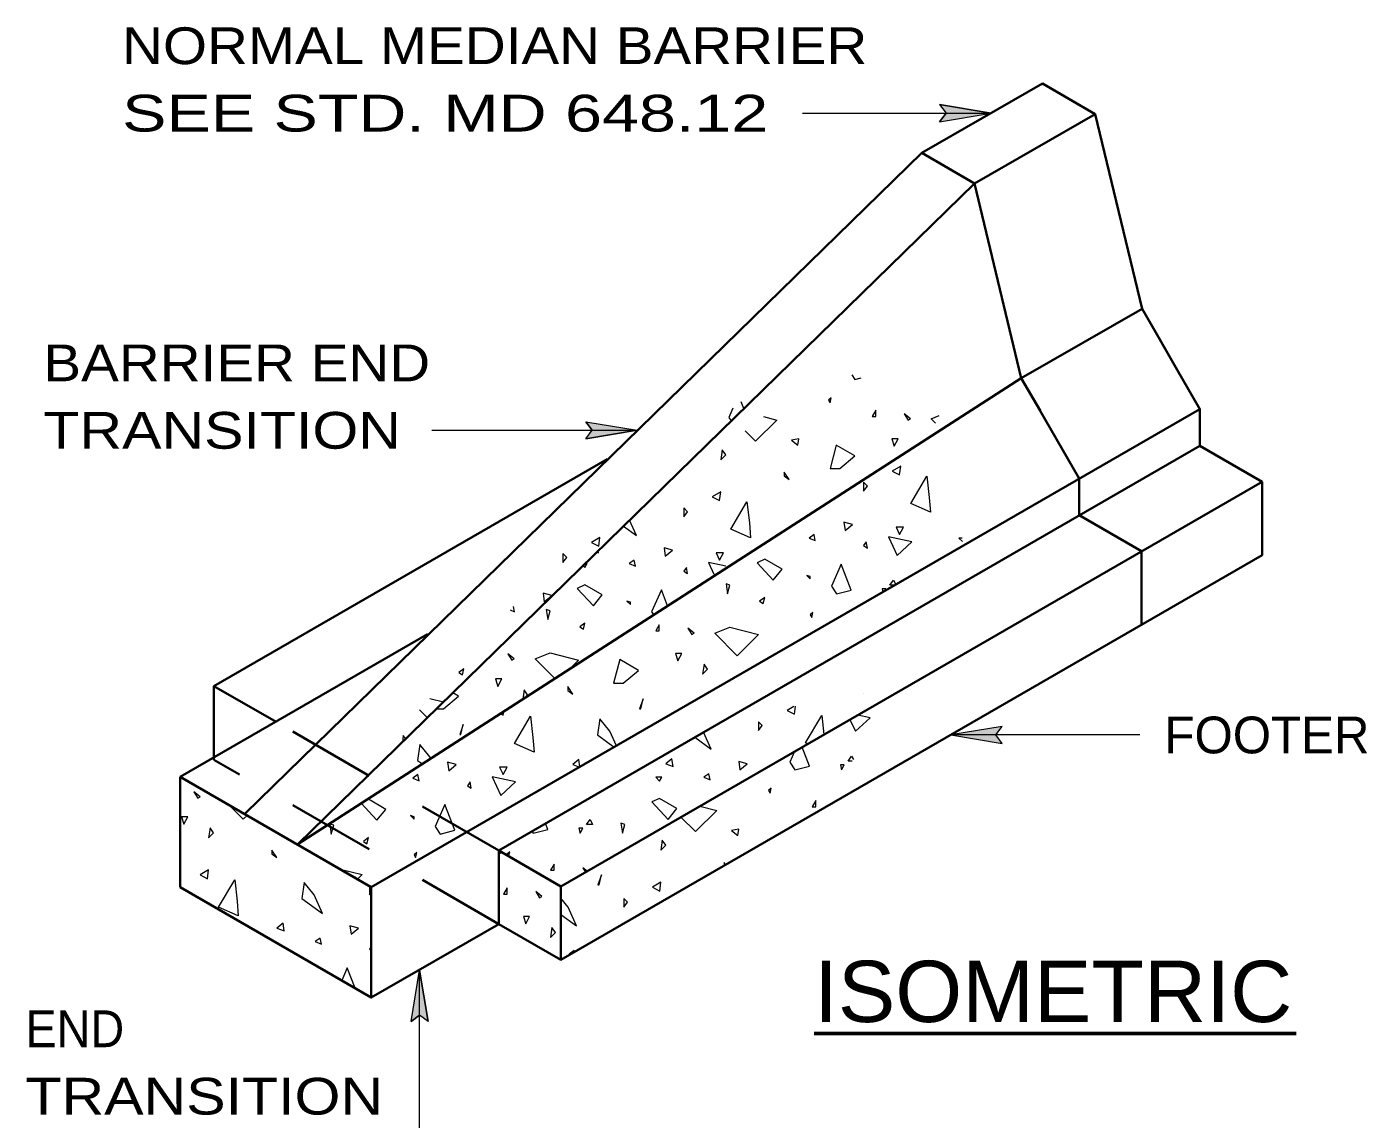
# Model space of a CAD drawing. Extents: x -11.7 to -4.5, y 8.6 to 18.8.
# Drawn here: x -11.741 to -9.555, y 17.003 to 18.786 of the extents above; entities that cross this region are included whole.
import ezdxf
from ezdxf.enums import TextEntityAlignment as Align

# ---------------------------------------------------------------- set-up
doc = ezdxf.new("R2010")
doc.units = 0
doc.header["$LTSCALE"] = 0.024
doc.linetypes.add('LONG_DASHED', pattern=[7.5, 6, -1.5])
for name, color, linetype, lineweight in [('1', 7, 'Continuous', 35), ('10', 7, 'Continuous', 13), ('12', 7, 'Continuous', 53), ('6', 7, 'Continuous', 13)]:
    doc.layers.add(name, color=color, linetype=linetype, lineweight=lineweight)

msp = doc.modelspace()

# ---------------------------------------------------------------- hatches: boundary and pattern name
at = {"layer": '10'}
for points in [[(-10.1685, 18.64483), (-10.2525, 18.65883), (-10.242, 18.64483), (-10.2525, 18.63083)], [(-10.74567, 18.12733), (-10.82967, 18.11333), (-10.81917, 18.12733), (-10.82967, 18.14133)], [(-10.15033, 17.64433), (-10.23433, 17.63033), (-10.15033, 17.61633), (-10.16083, 17.63033)], [(-11.1005, 17.24683), (-11.0865, 17.16283), (-11.1005, 17.17333), (-11.1145, 17.16283)]]:
    msp.add_hatch(color=256, dxfattribs=at).paths.add_polyline_path(points)

# ---------------------------------------------------------------- linework, layer by layer
at = {"layer": '1'}
for p, q in [((-10.08467, 18.693), (-10.28133, 18.57983)), ((-9.99883, 18.64333), (-10.08467, 18.693)), ((-9.9225, 18.32567), (-9.99883, 18.64333)), ((-10.28133, 18.57983), (-11.385, 17.502)), ((-10.1955, 18.53017), (-10.28133, 18.57983)), ((-9.9225, 18.32567), (-10.11933, 18.2125)), ((-9.892, 18.27283), (-9.9225, 18.32567)), ((-10.11933, 18.2125), (-11.29917, 17.45233)), ((-9.72683, 18.0435), (-9.828, 18.102)), ((-10.87017, 17.38333), (-9.72683, 18.0435)), ((-10.02483, 17.98883), (-10.02483, 18.04883)), ((-9.9235, 17.93033), (-10.02483, 17.98883)), ((-9.9235, 17.81033), (-9.9235, 17.93033)), ((-11.49117, 17.56183), (-11.0875, 17.795)), ((-11.436, 17.59), (-11.436, 17.71)), ((-11.17933, 17.38183), (-11.49117, 17.56183)), ((-11.49117, 17.38183), (-11.49117, 17.56183)), ((-11.17933, 17.20183), (-11.49117, 17.38183)), ((-10.87017, 17.26333), (-10.87017, 17.38333))]:
    msp.add_line(p, q, dxfattribs=at)
at = {"layer": '1', "linetype": 'LONG_DASHED'}
for p, q in [((-10.97133, 17.44183), (-11.334, 17.65117)), ((-10.97133, 17.32183), (-11.436, 17.59))]:
    msp.add_line(p, q, dxfattribs=at)
at = {"layer": '1'}
for points in [[(-9.99883, 18.64333), (-10.1955, 18.53017), (-11.29917, 17.45233)], [(-10.08867, 18.15967), (-10.11933, 18.2125), (-10.1955, 18.53017)], [(-9.828, 18.102), (-9.828, 18.162), (-9.86517, 18.22617), (-9.90217, 18.2905)], [(-10.02483, 18.04883), (-10.06183, 18.113), (-10.099, 18.17717)], [(-10.97133, 17.32183), (-11.17933, 17.20183), (-11.17933, 17.38183), (-9.828, 18.162)], [(-10.87017, 17.38333), (-10.97133, 17.44183), (-9.828, 18.102)], [(-11.33467, 17.6515), (-11.436, 17.71), (-10.7945, 18.08033)], [(-10.87017, 17.26333), (-9.72683, 17.9235), (-9.72683, 18.0435)], [(-10.87017, 17.26333), (-10.97133, 17.32183), (-10.97133, 17.44183)]]:
    msp.add_lwpolyline(points, dxfattribs=at)
at = {"layer": '10'}
for p, q in [((-10.2525, 18.65883), (-10.1685, 18.64483)), ((-10.2525, 18.65883), (-10.242, 18.64483)), ((-10.476, 18.64483), (-10.1685, 18.64483)), ((-10.2525, 18.63083), (-10.1685, 18.64483)), ((-10.2525, 18.63083), (-10.242, 18.64483)), ((-11.08067, 18.12733), (-10.74567, 18.12733)), ((-10.82967, 18.14133), (-10.74567, 18.12733)), ((-10.82967, 18.14133), (-10.81917, 18.12733)), ((-10.82967, 18.11333), (-10.74567, 18.12733)), ((-10.82967, 18.11333), (-10.81917, 18.12733)), ((-9.926, 17.63033), (-10.23433, 17.63033)), ((-11.1145, 17.16283), (-11.1005, 17.24683)), ((-11.0865, 17.16283), (-11.1005, 17.24683)), ((-11.1145, 17.16283), (-11.1005, 17.17333)), ((-11.0865, 17.16283), (-11.1005, 17.17333))]:
    msp.add_line(p, q, dxfattribs=at)
for points in [[(-10.1685, 18.64483), (-10.2525, 18.65883), (-10.242, 18.64483), (-10.2525, 18.63083)], [(-10.74567, 18.12733), (-10.82967, 18.11333), (-10.81917, 18.12733), (-10.82967, 18.14133)], [(-10.15033, 17.64433), (-10.23433, 17.63033), (-10.15033, 17.61633), (-10.16083, 17.63033)], [(-11.1005, 17.24683), (-11.0865, 17.16283), (-11.1005, 17.17333), (-11.1145, 17.16283)]]:
    msp.add_lwpolyline(points, close=True, dxfattribs=at)
msp.add_lwpolyline([(-11.54833, 16.931), (-11.1005, 16.931), (-11.1005, 17.24683)], dxfattribs=at)
at = {"layer": '12'}
msp.add_line((-10.45717, 17.1435), (-9.671, 17.1435), dxfattribs=at)
at = {"layer": '6'}
for p, q in [((-10.49, 18.243), (-10.48983, 18.24267)), ((-10.48733, 18.245), (-10.4875, 18.245)), ((-10.57183, 18.16267), (-10.57633, 18.174)), ((-11.08383, 17.68983), (-11.06167, 17.68417)), ((-11.08783, 17.6585), (-11.1005, 17.67117)), ((-11.17933, 17.38117), (-11.181, 17.38283))]:
    msp.add_line(p, q, dxfattribs=at)
for points in [[(-10.39567, 18.21767), (-10.39083, 18.21033), (-10.38067, 18.21317)], [(-10.58967, 18.16333), (-10.59617, 18.1485), (-10.59233, 18.14267)], [(-10.53967, 18.14967), (-10.51817, 18.14417), (-10.55267, 18.10967), (-10.56983, 18.12667)], [(-10.25917, 18.139), (-10.26617, 18.146), (-10.25317, 18.15133)], [(-10.76783, 17.97117), (-10.74667, 17.956), (-10.758, 17.98067)], [(-10.21583, 17.95167), (-10.221, 17.95167), (-10.21517, 17.94583)], [(-10.8115, 17.9285), (-10.809, 17.92767), (-10.8095, 17.9305)], [(-10.834, 17.9065), (-10.83117, 17.90367), (-10.82733, 17.90983), (-10.8305, 17.90983)], [(-10.60133, 17.90583), (-10.6295, 17.91183), (-10.6205, 17.89283)], [(-10.32533, 17.87483), (-10.33383, 17.87483), (-10.328, 17.883), (-10.32417, 17.87567)], [(-10.69633, 17.84117), (-10.70633, 17.86717), (-10.72217, 17.83117), (-10.71883, 17.82617)], [(-10.34167, 17.86533), (-10.34, 17.86867), (-10.34633, 17.86867), (-10.34517, 17.8635)], [(-10.95283, 17.83433), (-10.94567, 17.83117), (-10.94733, 17.84017)], [(-10.88017, 17.72233), (-10.91233, 17.75433), (-10.88783, 17.7645), (-10.84117, 17.75233), (-10.85567, 17.738)], [(-10.52083, 17.762), (-10.524, 17.7615), (-10.523, 17.76083)], [(-11.07283, 17.67317), (-11.0615, 17.67317), (-11.03717, 17.69383), (-11.04633, 17.69917)], [(-10.92983, 17.69017), (-10.92433, 17.69583), (-10.93, 17.704), (-10.93233, 17.68867)], [(-10.37617, 17.69867), (-10.37617, 17.6985), (-10.37617, 17.69867)], [(-10.96883, 17.665), (-10.96417, 17.66267), (-10.96333, 17.66867)], [(-10.49017, 17.67683), (-10.50133, 17.67017), (-10.48933, 17.664), (-10.48767, 17.67733)], [(-10.4675, 17.61583), (-10.47117, 17.6175), (-10.44483, 17.662), (-10.44133, 17.631)], [(-10.39883, 17.6555), (-10.38983, 17.63633), (-10.36583, 17.6585), (-10.38617, 17.66283)], [(-10.7795, 17.61267), (-10.79033, 17.63633), (-10.80667, 17.6565), (-10.8105, 17.6305), (-10.783, 17.61067)], [(-11.12317, 17.624), (-11.12717, 17.62967), (-11.12867, 17.61867)], [(-10.6515, 17.62667), (-10.62483, 17.60733), (-10.63733, 17.63483)], [(-11.0825, 17.59183), (-11.08367, 17.5945), (-11.1, 17.61467), (-11.10383, 17.58867), (-11.096, 17.58317)], [(-10.48933, 17.60333), (-10.49683, 17.586), (-10.48867, 17.5735), (-10.46467, 17.57967), (-10.47667, 17.61067)], [(-10.39517, 17.58783), (-10.40183, 17.58783), (-10.396, 17.596), (-10.39317, 17.5905)], [(-10.839, 17.57833), (-10.84083, 17.59017), (-10.85083, 17.582), (-10.83967, 17.578)], [(-11.38183, 17.49883), (-11.388, 17.49283), (-11.4105, 17.51533)], [(-11.25083, 17.4995), (-11.23733, 17.51183), (-11.238, 17.512)], [(-11.19583, 17.51883), (-11.17017, 17.49133), (-11.15567, 17.509), (-11.184, 17.52533), (-11.19, 17.52267)], [(-10.64333, 17.51433), (-10.616, 17.50733), (-10.6505, 17.47267), (-10.67433, 17.4965)], [(-10.91733, 17.47317), (-10.91517, 17.47), (-10.89117, 17.47633), (-10.895, 17.486)], [(-10.51867, 17.46633), (-10.519, 17.4665), (-10.51917, 17.466)], [(-10.97133, 17.4365), (-10.96783, 17.43733), (-10.969, 17.4405)], [(-10.95533, 17.43267), (-10.95367, 17.43983), (-10.958, 17.436), (-10.9565, 17.43317)], [(-10.6015, 17.4185), (-10.604, 17.42233), (-10.604, 17.417)], [(-11.23017, 17.41167), (-11.19417, 17.4025), (-11.20167, 17.395)], [(-11.22367, 17.4075), (-11.22417, 17.406), (-11.22233, 17.406), (-11.22217, 17.40667)], [(-10.82733, 17.408), (-10.8345, 17.41383), (-10.83, 17.4065)], [(-11.182, 17.3835), (-11.182, 17.3695), (-11.17933, 17.373)], [(-10.87017, 17.3375), (-10.8445, 17.319), (-10.85833, 17.34933), (-10.87017, 17.36383)], [(-11.17933, 17.2845), (-11.182, 17.28067), (-11.17933, 17.279)], [(-10.84783, 17.27633), (-10.84833, 17.27867), (-10.8565, 17.273), (-10.85483, 17.27233)], [(-11.20567, 17.217), (-11.2185, 17.25033), (-11.2275, 17.22967)]]:
    msp.add_lwpolyline(points, dxfattribs=at)
for points in [[(-10.42933, 18.18017), (-10.43367, 18.17633), (-10.43117, 18.172)], [(-10.35683, 18.16), (-10.36267, 18.15), (-10.35683, 18.15)], [(-10.304, 18.14417), (-10.30017, 18.146), (-10.31033, 18.15417)], [(-10.49417, 18.1115), (-10.484, 18.10333), (-10.48217, 18.1135)], [(-10.41533, 18.065), (-10.39083, 18.08567), (-10.42117, 18.10333), (-10.43117, 18.065)], [(-10.3305, 18.1135), (-10.3265, 18.1015), (-10.32033, 18.1135)], [(-10.607, 18.09567), (-10.60933, 18.07933), (-10.60117, 18.0875)], [(-10.50617, 18.05917), (-10.50617, 18.053), (-10.498, 18.04717)], [(-10.33, 18.06067), (-10.318, 18.0545), (-10.316, 18.06883)], [(-10.3765, 18.0425), (-10.3765, 18.028), (-10.37033, 18.03617)], [(-10.2695, 18.018), (-10.2675, 17.994), (-10.29967, 18.00783), (-10.27333, 18.0525)], [(-10.62333, 18.01883), (-10.61133, 18.01267), (-10.60933, 18.027)], [(-10.66983, 18.00067), (-10.66983, 17.98617), (-10.66367, 17.99433)], [(-10.56283, 17.97617), (-10.56083, 17.95217), (-10.593, 17.966), (-10.56667, 18.01067)], [(-10.40867, 17.97767), (-10.40683, 17.96367), (-10.39483, 17.97383)], [(-10.32367, 17.9695), (-10.318, 17.9575), (-10.31167, 17.9695)], [(-10.82033, 17.9445), (-10.80833, 17.93833), (-10.8065, 17.95267)], [(-10.46533, 17.95167), (-10.45533, 17.94733), (-10.45717, 17.9575)], [(-10.3765, 17.93917), (-10.37033, 17.93533), (-10.37217, 17.9455)], [(-10.33617, 17.95367), (-10.32183, 17.92333), (-10.29783, 17.9455)], [(-10.867, 17.92633), (-10.867, 17.91183), (-10.86067, 17.92)], [(-10.702, 17.93583), (-10.7, 17.92183), (-10.688, 17.932)], [(-10.617, 17.92767), (-10.61133, 17.91567), (-10.605, 17.92767)], [(-10.75867, 17.90983), (-10.7485, 17.9055), (-10.7505, 17.91567)], [(-10.66983, 17.89733), (-10.66367, 17.8935), (-10.6655, 17.90367)], [(-10.55033, 17.91133), (-10.524, 17.883), (-10.5095, 17.90083), (-10.53783, 17.91717)], [(-10.42067, 17.8605), (-10.39667, 17.86667), (-10.413, 17.909), (-10.42883, 17.873)], [(-10.4635, 17.88883), (-10.46917, 17.89067), (-10.4635, 17.885)], [(-10.89917, 17.8615), (-10.89717, 17.8475), (-10.88517, 17.85767)], [(-10.84367, 17.8695), (-10.81717, 17.84117), (-10.80283, 17.859), (-10.83117, 17.87533)], [(-10.60067, 17.87683), (-10.59833, 17.8605), (-10.5945, 17.87483)], [(-10.75667, 17.847), (-10.7625, 17.84883), (-10.75667, 17.84317)], [(-10.546, 17.8485), (-10.54033, 17.84467), (-10.53783, 17.85467)], [(-10.894, 17.835), (-10.89167, 17.81867), (-10.88783, 17.833)], [(-10.45917, 17.83017), (-10.4635, 17.82633), (-10.461, 17.822)], [(-10.83933, 17.80667), (-10.8335, 17.80283), (-10.83117, 17.81283)], [(-10.70967, 17.81), (-10.7155, 17.8), (-10.70967, 17.8)], [(-10.65683, 17.79417), (-10.653, 17.79617), (-10.66317, 17.80433)], [(-10.5945, 17.80617), (-10.548, 17.79417), (-10.5825, 17.75967), (-10.619, 17.79617)], [(-10.95017, 17.75233), (-10.94633, 17.75433), (-10.9565, 17.7625)], [(-10.76833, 17.715), (-10.74383, 17.73567), (-10.774, 17.75333), (-10.78417, 17.715)], [(-10.68333, 17.7635), (-10.6795, 17.7515), (-10.67317, 17.7635)], [(-11.03633, 17.73233), (-11.03067, 17.7285), (-11.02833, 17.7385)], [(-10.63667, 17.74567), (-10.63917, 17.72933), (-10.631, 17.7375)], [(-10.97667, 17.72167), (-10.97283, 17.70967), (-10.9665, 17.72167)], [(-10.859, 17.70917), (-10.859, 17.703), (-10.85083, 17.69717)], [(-10.74183, 17.67283), (-10.74, 17.67283), (-10.73617, 17.68917)], [(-11.03517, 17.631), (-11.03333, 17.631), (-11.02933, 17.64733)], [(-10.91567, 17.62617), (-10.91383, 17.60217), (-10.946, 17.61617), (-10.9195, 17.66083)], [(-10.548, 17.652), (-10.548, 17.63767), (-10.54167, 17.64583)], [(-11.05483, 17.58583), (-11.053, 17.572), (-11.041, 17.582)], [(-10.97, 17.57767), (-10.96417, 17.56567), (-10.958, 17.57767)], [(-10.68917, 17.5915), (-10.69917, 17.58333), (-10.68717, 17.579)], [(-10.58017, 17.58717), (-10.57817, 17.57333), (-10.56617, 17.58333)], [(-10.41433, 17.58167), (-10.41233, 17.5735), (-10.408, 17.58167)], [(-11.1115, 17.56), (-11.1015, 17.55567), (-11.10333, 17.56567)], [(-11.02267, 17.5475), (-11.0165, 17.54367), (-11.01833, 17.55367)], [(-10.98233, 17.56183), (-10.968, 17.53167), (-10.944, 17.55367)], [(-10.7155, 17.56133), (-10.70933, 17.555), (-10.7055, 17.56133)], [(-10.63683, 17.56133), (-10.62667, 17.557), (-10.62867, 17.567)], [(-11.46233, 17.52733), (-11.4585, 17.52933), (-11.46867, 17.5375)], [(-10.52717, 17.54333), (-10.5315, 17.5395), (-10.529, 17.53517)], [(-11.06683, 17.46867), (-11.04283, 17.475), (-11.05917, 17.51717), (-11.075, 17.48117)], [(-10.72183, 17.521), (-10.69533, 17.49267), (-10.681, 17.51033), (-10.70933, 17.52667)], [(-10.45467, 17.52317), (-10.46033, 17.513), (-10.45467, 17.513)], [(-11.48883, 17.49667), (-11.485, 17.48467), (-11.47867, 17.49667)], [(-11.10967, 17.497), (-11.11533, 17.499), (-11.10967, 17.49317)], [(-10.8225, 17.49267), (-10.81833, 17.4845), (-10.82833, 17.4845)], [(-11.44217, 17.47883), (-11.44467, 17.4625), (-11.4365, 17.47067)], [(-11.247, 17.485), (-11.2445, 17.46867), (-11.24067, 17.48317)], [(-10.84083, 17.47817), (-10.83883, 17.47), (-10.8345, 17.47817)], [(-10.77217, 17.48633), (-10.76983, 17.47), (-10.766, 17.4845)], [(-10.592, 17.47467), (-10.58183, 17.4665), (-10.58, 17.4765)], [(-11.19217, 17.45667), (-11.1865, 17.45283), (-11.184, 17.463)], [(-10.70483, 17.45883), (-10.70717, 17.4425), (-10.699, 17.45067)], [(-11.34133, 17.44233), (-11.34133, 17.43617), (-11.33317, 17.43033)], [(-11.10533, 17.4385), (-11.10967, 17.43467), (-11.10717, 17.43033)], [(-11.4585, 17.402), (-11.4465, 17.39583), (-11.44467, 17.41017)], [(-10.88117, 17.41967), (-10.88683, 17.4095), (-10.88117, 17.4095)], [(-10.80983, 17.38583), (-10.808, 17.38583), (-10.80417, 17.40217)], [(-11.398, 17.35933), (-11.39617, 17.33533), (-11.42833, 17.34933), (-11.40183, 17.394)], [(-11.289, 17.38967), (-11.29283, 17.36367), (-11.25883, 17.33917), (-11.27267, 17.3695)], [(-10.95783, 17.38083), (-10.9635, 17.37067), (-10.95783, 17.37067)], [(-10.721, 17.382), (-10.709, 17.37567), (-10.70717, 17.39017)], [(-10.905, 17.36483), (-10.90117, 17.36683), (-10.91117, 17.375)], [(-10.76767, 17.36367), (-10.76767, 17.34933), (-10.76133, 17.3575)], [(-10.93133, 17.33417), (-10.9275, 17.32217), (-10.92133, 17.33417)], [(-11.32317, 17.32333), (-11.33317, 17.31517), (-11.32117, 17.31083)], [(-11.21417, 17.319), (-11.21217, 17.30517), (-11.20017, 17.31517)], [(-10.88483, 17.3165), (-10.88717, 17.30017), (-10.879, 17.30833)], [(-11.27083, 17.29317), (-11.26067, 17.28883), (-11.26267, 17.29883)]]:
    msp.add_lwpolyline(points, close=True, dxfattribs=at)

# ---------------------------------------------------------------- texts
at = {"layer": '12'}
for s, width, p in [('NORMAL MEDIAN BARRIER', 1.15, (-11.58567, 18.72475)), ('SEE STD. MD 648.12', 1.35, (-11.58567, 18.61475)), ('BARRIER END', 1.15, (-11.71408, 18.20733)), ('TRANSITION', 1.2, (-11.71408, 18.09733)), ('END', 0.95, (-11.74325, 17.121)), ('TRANSITION', 1.2, (-11.74325, 17.011))]:
    msp.add_text(s, height=0.06001, dxfattribs=dict(at, width=width)).set_placement(p)
msp.add_text('FOOTER', height=0.06001, dxfattribs=at).set_placement((-9.88592, 17.60033))
at = {"layer": '12', "width": 1.05}
msp.add_text('ISOMETRIC', height=0.1, dxfattribs=at).set_placement((-10.06746, 17.162), align=Align.CENTER)

doc.saveas('drawing.dxf')
